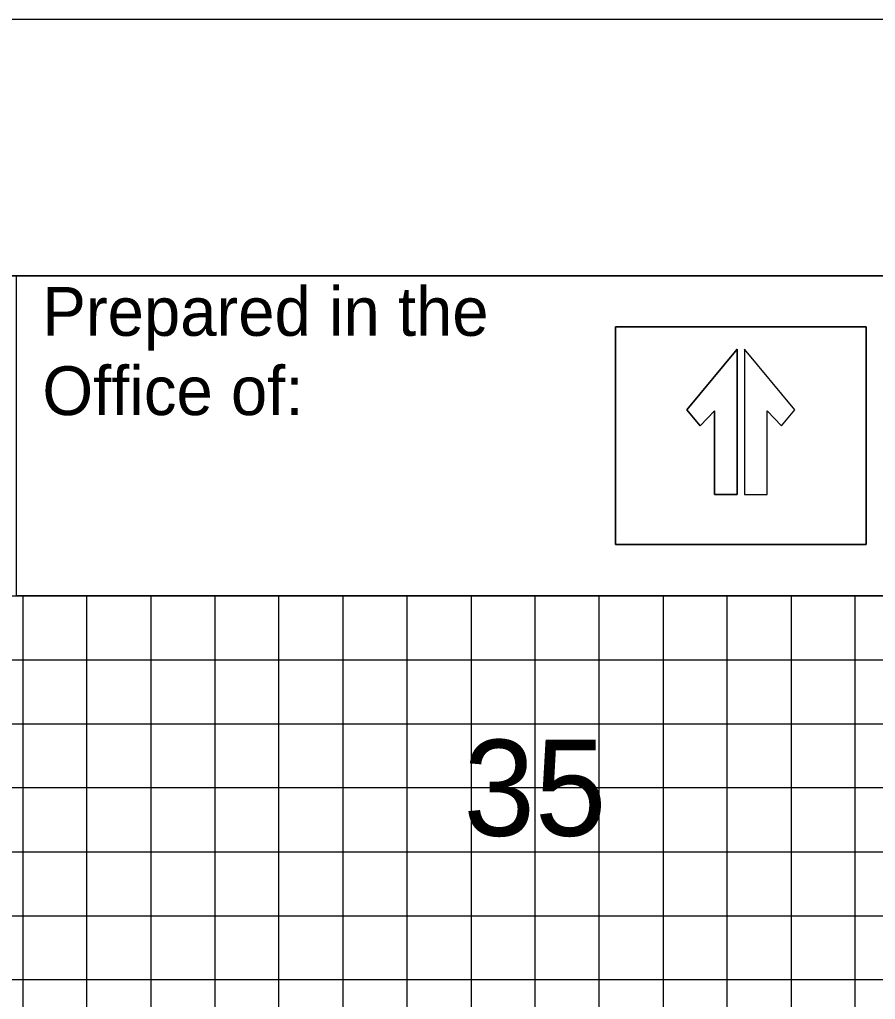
# Model space of a CAD drawing. Extents: x -7 to 162, y -2 to 327.
# Drawn here: x 110.98 to 117.66, y 99.35 to 107 of the extents above; entities that cross this region are included whole.
import ezdxf

# ---------------------------------------------------------------- set-up
doc = ezdxf.new("R2010")
doc.units = 0
for name, color, linetype in [('Exist Cross Section Cell', 7, 'Continuous'), ('Prop CMT Guardrail Widen Shoulder', 7, 'Continuous'), ('Prop CMT Pvmt Course 3', 7, 'Continuous'), ('Prop CMT Shld Paved Course 1', 7, 'Continuous'), ('Prop CMT Shld Paved Course 2', 7, 'Continuous'), ('Prop CMT Shld Paved Course 3', 7, 'Continuous'), ('Prop CMT Slope Grass', 7, 'Continuous'), ('Prop CMT Subgrade Earthwork', 7, 'Continuous'), ('Prop XS Earthwork Shape', 7, 'Continuous'), ('Scratch_Level_0', 7, 'Continuous'), ('Scratch_Level_3', 7, 'Continuous')]:
    doc.layers.add(name, color=color, linetype=linetype)

msp = doc.modelspace()

# ---------------------------------------------------------------- linework, layer by layer
at = {"layer": 'Prop CMT Guardrail Widen Shoulder'}
msp.add_lwpolyline([(110.9512, 105), (130, 105), (130, 102.5), (110.9512, 102.5)], close=True, dxfattribs=at)
at = {"layer": 'Prop CMT Pvmt Course 3'}
msp.add_lwpolyline([(-6.7, -2.5), (161.65, -2.5), (161.65, 107), (-6.7, 107)], close=True, dxfattribs=at)
at = {"layer": 'Prop CMT Shld Paved Course 1'}
msp.add_line((0, 102), (160, 102), dxfattribs=at)
for points in [[(0, 101.5), (135, 101.5), (160, 101.5)], [(160, 101), (0, 101)], [(0, 100.5), (160, 100.5)], [(160, 99.5), (0, 99.5)]]:
    msp.add_lwpolyline(points, dxfattribs=at)
at = {"layer": 'Prop CMT Shld Paved Course 2'}
msp.add_lwpolyline([(160, 105), (0, 105), (0, 0), (160, 0)], close=True, dxfattribs=at)
at = {"layer": 'Prop CMT Shld Paved Course 3'}
for points in [[(110, 0), (110.5, 0), (110.5, 105), (111, 105)], [(111.5, 105), (112, 105)], [(113, 105), (113.5, 105)], [(114, 105), (114.5, 105)], [(115.5, 105), (116, 105)], [(116.5, 105), (117, 105)], [(111, 102.5), (111, 0)], [(111, 0), (111.5, 0), (111.5, 102.5)], [(112, 102.5), (112, 0)], [(112.5, 0), (113, 0), (113, 102.5)], [(113.5, 102.5), (113.5, 0)], [(113.5, 0), (114, 0), (114, 102.5)], [(114.5, 102.5), (114.5, 0)], [(115, 0), (115.5, 0), (115.5, 102.5)], [(116, 102.5), (116, 0)], [(116, 0), (116.5, 0), (116.5, 102.5)], [(117, 102.5), (117, 0)]]:
    msp.add_lwpolyline(points, dxfattribs=at)
at = {"layer": 'Prop CMT Slope Grass'}
for points in [[(72.5, 0), (77.5, 0), (77.5, 105), (82.5, 105), (82.5, 0), (87.5, 0), (87.5, 105), (92.5, 105), (92.5, 0), (97.5, 0), (97.5, 105), (102.5, 105), (102.5, 0), (107.5, 0), (107.5, 105), (112.5, 105)], [(117.5, 105), (122.5, 105)], [(0, 102.5), (137.5, 102.5)], [(112.5, 102.5), (112.5, 0), (117.5, 0), (117.5, 102.5)]]:
    msp.add_lwpolyline(points, dxfattribs=at)
at = {"layer": 'Prop CMT Subgrade Earthwork'}
msp.add_lwpolyline([(-5.4, -0.5), (161.2, -0.5), (161.2, 105), (-5.4, 105)], close=True, dxfattribs=at)
at = {"layer": 'Prop XS Earthwork Shape'}
for points in [[(117.584, 104.5995), (115.6266, 104.5995), (115.6266, 102.9005), (117.584, 102.9005), (117.584, 104.5995)], [(116.5788, 104.4257), (116.5788, 103.2897), (116.3999, 103.2897), (116.3999, 103.945), (116.2891, 103.8276), (116.1849, 103.9521), (116.5788, 104.4257)], [(116.1849, 103.9521), (116.2891, 103.8276), (116.3999, 103.945), (116.3999, 103.2897), (116.5788, 103.2897), (116.5788, 104.4257), (116.1849, 103.9521)], [(116.6339, 104.4257), (116.6339, 103.2897), (116.8129, 103.2897), (116.8129, 103.945), (116.9237, 103.8276), (117.0279, 103.9521), (116.6339, 104.4257)]]:
    msp.add_lwpolyline(points, dxfattribs=at)
for points in [[(115.6266, 104.5995), (117.584, 104.5995), (117.584, 102.9005), (115.6266, 102.9005)], [(116.6339, 104.4257), (116.6339, 103.2897), (116.8129, 103.2897), (116.8129, 103.945), (116.9237, 103.8276), (117.0279, 103.9521)]]:
    msp.add_lwpolyline(points, close=True, dxfattribs=at)
at = {"layer": 'Scratch_Level_3'}
for p, q in [((115, 105), (110, 105)), ((115, 0), (115, 102.5))]:
    msp.add_line(p, q, dxfattribs=at)
msp.add_lwpolyline([(0, 100), (160, 100)], dxfattribs=at)

# ---------------------------------------------------------------- texts
at = {"layer": 'Exist Cross Section Cell'}
msp.add_text('35', height=0.75, dxfattribs=at).set_placement((114.4408, 100.625))
at = {"layer": 'Scratch_Level_0'}
for s, height, p in [('Prepared in the ', 0.380976, (111.1533, 104.5302)), ('Office of:', 0.38098, (111.1533, 103.9112))]:
    msp.add_text(s, height=height, rotation=360, dxfattribs=at).set_placement(p)

doc.saveas('drawing.dxf')
